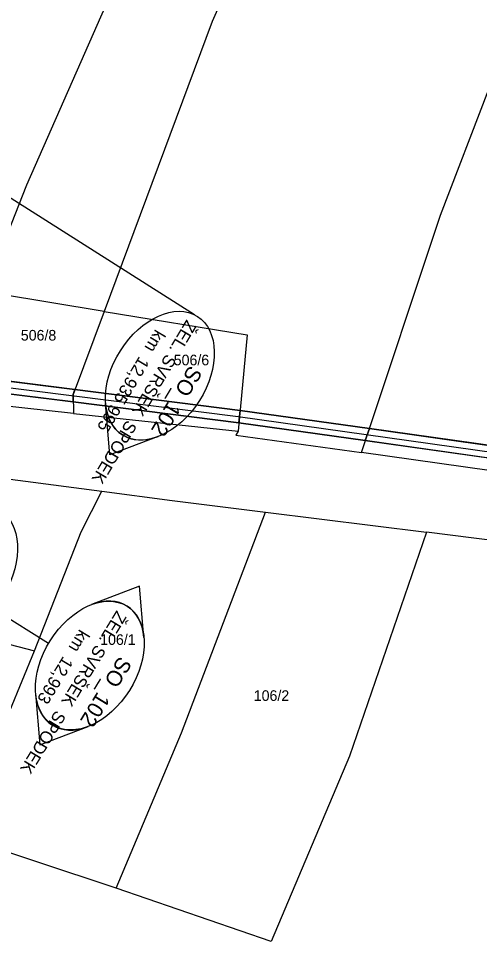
# Model space of a CAD drawing. Extents: x -746176 to -739709, y -1128407 to -1124482.
# Drawn here: x -743114.2 to -743040.3, y -1127186.1 to -1127038.1 of the extents above; entities that cross this region are included whole.
import ezdxf

# ---------------------------------------------------------------- set-up
doc = ezdxf.new("R2010")
doc.units = 0
for name, color, linetype in [('Vrstva 21', 7, 'Continuous'), ('Vrstva 23', 7, 'Continuous'), ('Vrstva 30', 7, 'Continuous'), ('Vrstva 32', 7, 'Continuous'), ('Vrstva 33', 7, 'Continuous'), ('Vrstva 35', 7, 'Continuous'), ('Vrstva 42', 7, 'Continuous'), ('Vrstva 6', 7, 'Continuous')]:
    doc.layers.add(name, color=color, linetype=linetype)

msp = doc.modelspace()

# ---------------------------------------------------------------- linework, layer by layer
at = {"layer": 'Vrstva 21'}
for p, q in [((-743122.55, -1127095.4), (-743105.2, -1127097.59)), ((-743105.47, -1127099.57), (-743122.74, -1127097.4)), ((-743105.2, -1127097.59), (-743105.49, -1127098.37)), ((-743105.19, -1127097.59), (-743078.69, -1127100.93)), ((-743105.49, -1127098.37), (-743105.47, -1127099.57)), ((-743078.88, -1127102.92), (-743105.47, -1127099.57)), ((-743078.69, -1127100.93), (-743078.88, -1127102.92)), ((-743078.69, -1127100.93), (-743057.95, -1127103.84)), ((-743058.6, -1127105.77), (-743078.88, -1127102.92)), ((-743057.95, -1127103.84), (-743058.6, -1127105.77)), ((-743057.95, -1127103.84), (-743016.88, -1127109.62)), ((-743017.2, -1127111.6), (-743058.6, -1127105.77))]:
    msp.add_line(p, q, dxfattribs=at)
at = {"layer": 'Vrstva 23'}
msp.add_lwpolyline([(-743154.26, -1127082.61), (-743159.25, -1127091.79), (-743078.98, -1127101.9), (-743017.04, -1127110.61), (-742993.93, -1127114.82), (-742964.82, -1127120.76), (-742937.74, -1127126.54), (-742940.65, -1127140.7), (-742943, -1127146.4)], dxfattribs=at)
at = {"layer": 'Vrstva 30'}
for p, q in [((-743086, -1127085.59), (-743143.43, -1127049.19)), ((-743109.42, -1127138.31), (-743174.12, -1127097.81))]:
    msp.add_line(p, q, dxfattribs=at)
at = {"layer": 'Vrstva 33'}
for p, q in [((-743100.51, -1127085.04), (-743119.42, -1127081.96)), ((-743105.44, -1127101.41), (-743122.95, -1127099.53)), ((-743105.44, -1127101.41), (-743079.01, -1127104.25)), ((-743171.62, -1127104.6), (-743100.85, -1127113.88)), ((-743074.61, -1127117.23), (-743048.8, -1127120.46)), ((-743121.01, -1127162.08), (-743111.68, -1127139.51))]:
    msp.add_line(p, q, dxfattribs=at)
for points in [[(-743119.42, -1127081.96), (-743118.49, -1127078.74), (-743112.93, -1127064.74), (-743067.57, -1126961.77), (-743055.18, -1126936.67)], [(-743041.11, -1126943.01), (-743050.16, -1126963.96), (-743083.16, -1127038.56), (-743100.51, -1127085.04)], [(-743059.24, -1127107.7), (-743046.52, -1127069.6), (-743031.05, -1127029.12), (-743017.87, -1126995.55), (-743011.05, -1126982.56)], [(-743100.51, -1127085.04), (-743105.49, -1127098.37), (-743105.44, -1127101.41)], [(-743100.51, -1127085.04), (-743077.54, -1127088.79), (-743079.01, -1127104.25)], [(-743079.01, -1127104.25), (-743079.38, -1127104.87), (-743059.24, -1127107.7)], [(-742996.77, -1127117.36), (-743017.52, -1127113.57), (-743059.24, -1127107.7)], [(-743111.68, -1127139.51), (-743104.19, -1127120.4), (-743100.85, -1127113.88)], [(-743100.85, -1127113.88), (-743089.57, -1127115.36), (-743074.61, -1127117.23)], [(-743098.58, -1127177.58), (-743088.09, -1127152.63), (-743074.61, -1127117.23)], [(-743048.8, -1127120.46), (-743061.12, -1127156.38), (-743073.7, -1127186.12), (-743098.58, -1127177.58)], [(-742989.3, -1127130.42), (-743021.39, -1127124.08), (-743033.19, -1127122.41), (-743048.8, -1127120.46)], [(-743183.01, -1127122.02), (-743160.92, -1127126.4), (-743152.69, -1127128.83), (-743111.68, -1127139.51)], [(-743098.58, -1127177.58), (-743123.94, -1127169.17), (-743121.01, -1127162.08)]]:
    msp.add_lwpolyline(points, dxfattribs=at)
at = {"layer": 'Vrstva 35'}
for p, q in [((-743099.58, -1127108.03), (-743100.27, -1127099.8)), ((-743099.58, -1127108.03), (-743100.27, -1127099.8)), ((-743091.85, -1127105.13), (-743099.58, -1127108.03)), ((-743091.85, -1127105.13), (-743099.58, -1127108.03)), ((-743094.84, -1127129.14), (-743102.55, -1127132.08)), ((-743094.84, -1127129.14), (-743102.55, -1127132.08)), ((-743094.11, -1127137.36), (-743094.84, -1127129.14)), ((-743094.11, -1127137.36), (-743094.84, -1127129.14)), ((-743111.53, -1127146.36), (-743110.8, -1127154.58)), ((-743111.53, -1127146.36), (-743110.8, -1127154.58)), ((-743110.8, -1127154.58), (-743103.09, -1127151.64)), ((-743110.8, -1127154.58), (-743103.09, -1127151.64))]:
    msp.add_line(p, q, dxfattribs=at)
for centre, major_axis in [((-743091.56, -1127095.35), (6.01, 9.51)), ((-743123.03, -1127126.57), (-5.72, -9.69)), ((-743102.8, -1127141.85), (-5.97, -9.53))]:
    msp.add_ellipse(centre, major_axis=major_axis, ratio=0.666667, dxfattribs=at)
for centre, major_axis in [((-743091.56, -1127095.35), (-6.02, -9.51)), ((-743102.8, -1127141.85), (5.97, 9.54)), ((-743102.84, -1127141.87), (-5.97, -9.54))]:
    msp.add_ellipse(centre, major_axis=major_axis, ratio=0.666473, start_param=5.557317, end_param=7.009053, dxfattribs=at)
at = {"layer": 'Vrstva 6'}
for points in [[(-743122.55, -1127095.4), (-743122.74, -1127097.4), (-743105.47, -1127099.57), (-743105.49, -1127098.37), (-743105.2, -1127097.59)], [(-743105.2, -1127097.59), (-743105.49, -1127098.37), (-743105.47, -1127099.57), (-743078.88, -1127102.92), (-743078.69, -1127100.93)], [(-743078.69, -1127100.93), (-743078.88, -1127102.92), (-743058.6, -1127105.77), (-743057.95, -1127103.84)], [(-743057.95, -1127103.84), (-743058.6, -1127105.77), (-743017.2, -1127111.6), (-742996.06, -1127115.45), (-742995.35, -1127113.55), (-743016.88, -1127109.62)]]:
    msp.add_lwpolyline(points, close=True, dxfattribs=at)

# ---------------------------------------------------------------- texts
at = {"layer": 'Vrstva 32'}
for s, height, rotation, p in [('ŽEL. SVRŠEK  SPODEK', 2, 239.1744, (-743087.27, -1127086.27)), ('km  12,935 995', 2, 239.1744, (-743092.27, -1127087.8)), ('SO_102', 2.5, 239.1744, (-743086.78, -1127093.56)), ('ŽEL. SVRŠEK  SPODEK', 2, 238.6088, (-743098.49, -1127132.92)), ('km  12,993', 2, 238.6088, (-743104.43, -1127135.92)), ('SO_102', 2.5, 238.6088, (-743098.07, -1127140.22))]:
    msp.add_text(s, height=height, rotation=rotation, dxfattribs=at).set_placement(p)
at = {"layer": 'Vrstva 42'}
for s, p in [('506/8', (-743113.87, -1127089.72)), ('506/6', (-743089.34, -1127093.69)), ('106/1', (-743101.14, -1127138.54)), ('106/2', (-743076.5, -1127147.52))]:
    msp.add_text(s, height=1.7, dxfattribs=at).set_placement(p)

doc.saveas('drawing.dxf')
